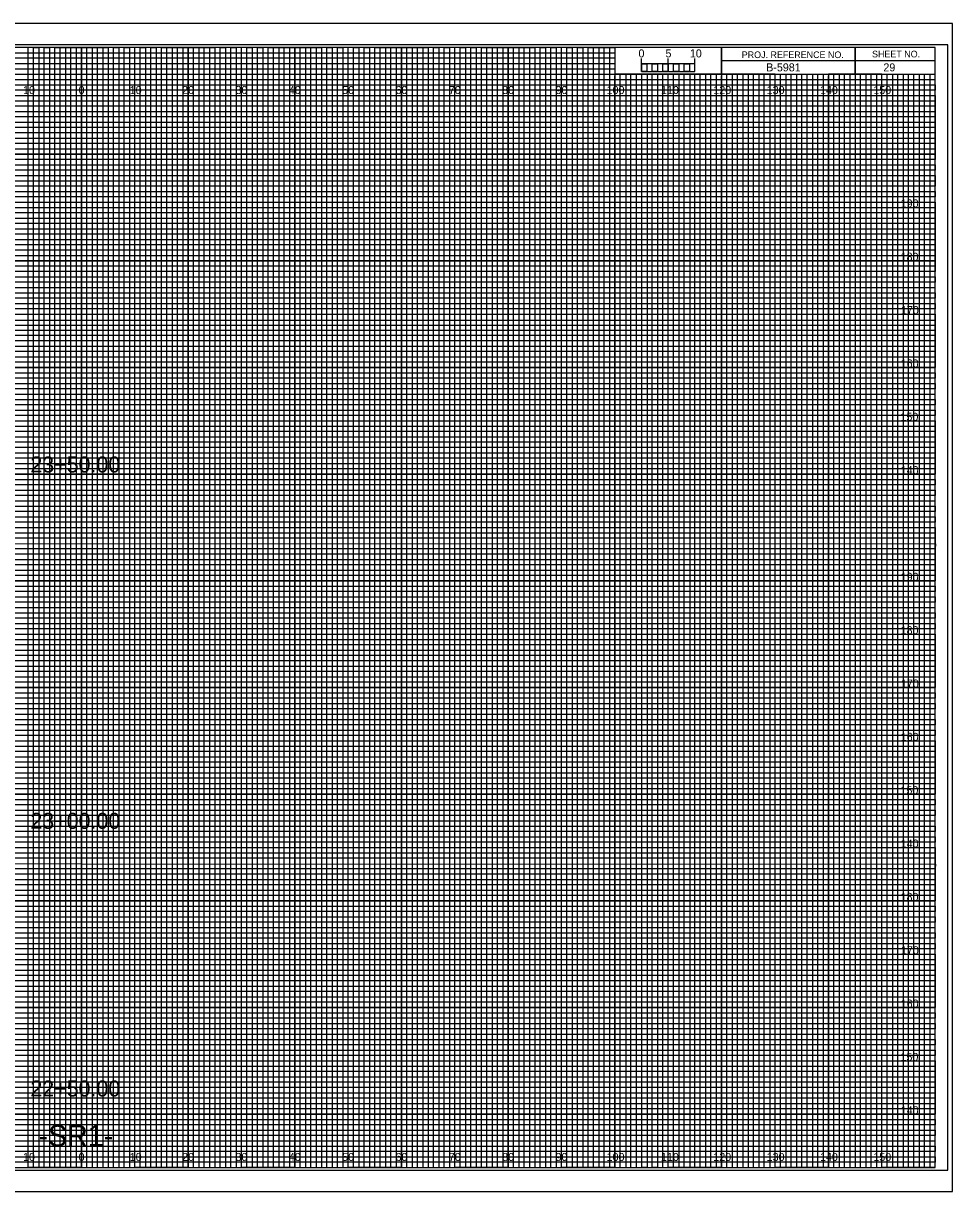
# Model space of a CAD drawing. Extents: x -13 to 323, y -5 to 654.
# Drawn here: x 149.1 to 323.3, y 215.5 to 434.5 of the extents above; entities that cross this region are included whole.
import ezdxf

# ---------------------------------------------------------------- set-up
doc = ezdxf.new("R2010")
doc.units = 0
for name, color, linetype in [('Exist Cross Section Cell', 7, 'Continuous'), ('Exist XS Center Line Elevation Label', 7, 'Continuous'), ('Exist XS Ground Line', 7, 'Continuous'), ('Prop CMT Concrete Structures', 7, 'Continuous'), ('Prop CMT Guardrail Graphics', 7, 'Continuous'), ('Prop CMT Pvmt Course 1', 7, 'Continuous'), ('Prop CMT Pvmt Course 2', 7, 'Continuous'), ('Prop CMT Pvmt Course 3', 7, 'Continuous'), ('Prop CMT Pvmt Surface', 7, 'Continuous'), ('Prop CMT Shld Paved Course 1', 7, 'Continuous'), ('Prop CMT Shld Paved Course 2', 7, 'Continuous'), ('Prop CMT Shld Paved Course 3', 7, 'Continuous'), ('Prop CMT Subgrade Earthwork', 7, 'Continuous'), ('Prop XS Ditch Standard Text', 7, 'Continuous'), ('Prop XS SE Text', 7, 'Continuous'), ('Prop XS Side Slope Text', 7, 'Continuous'), ('Scratch_Level_0', 7, 'Continuous')]:
    doc.layers.add(name, color=color, linetype=linetype)

msp = doc.modelspace()

# ---------------------------------------------------------------- linework, layer by layer
at = {"layer": 'Exist XS Center Line Elevation Label'}
for points in [[(145, 220), (155, 220), (155, 430), (165, 430), (165, 220), (175, 220), (175, 430), (185, 430), (185, 220), (195, 220), (195, 430), (205, 430), (205, 220), (215, 220), (215, 430), (225, 430), (225, 220), (235, 220), (235, 430), (245, 430), (245, 220), (255, 220), (255, 430), (259.93, 430), (260, 430), (260, 425), (264.99, 425), (264.99, 220), (275, 220), (275, 425), (285, 425), (285, 220), (295, 220), (295, 425), (305, 425), (305, 220), (315, 220), (315, 425)], [(0, 425), (275, 425)], [(0, 405), (320, 405), (320, 415), (0, 415)], [(0, 385), (320, 385), (320, 395), (0, 395)], [(0, 365), (320, 365), (320, 375), (0, 375)], [(0, 345), (320, 345), (320, 355), (0, 355)], [(0, 325), (320, 325), (320, 335), (0, 335)], [(0, 305), (320, 305), (320, 315), (0, 315)], [(0, 285), (320, 285), (320, 295), (0, 295)], [(0, 265), (320, 265), (320, 275), (0, 275)], [(0, 245), (320, 245), (320, 255), (0, 255)], [(0, 225), (320, 225), (320, 235), (0, 235)]]:
    msp.add_lwpolyline(points, dxfattribs=at)
at = {"layer": 'Exist XS Ground Line'}
for p, q in [((150, 430), (140, 430)), ((150, 220), (150, 430)), ((170, 430), (160, 430)), ((160, 430), (160, 220)), ((170, 220), (170, 430)), ((190, 430), (180, 430)), ((180, 430), (180, 220)), ((190, 220), (190, 430)), ((210, 430), (200, 430)), ((200, 430), (200, 220)), ((210, 220), (210, 430)), ((230, 430), (220, 430)), ((220, 430), (220, 220)), ((230, 220), (230, 430)), ((250, 430), (240, 430)), ((240, 430), (240, 220)), ((250, 220), (250, 430)), ((260, 430), (260, 220)), ((270, 220), (270, 425)), ((290, 425), (280, 425)), ((280, 425), (280, 220)), ((290, 220), (290, 425)), ((310, 425), (300, 425)), ((300, 425), (300, 220)), ((310, 220), (310, 425)), ((160, 220), (150, 220)), ((180, 220), (170, 220)), ((200, 220), (190, 220)), ((220, 220), (210, 220)), ((240, 220), (230, 220)), ((260, 220), (250, 220)), ((280, 220), (270, 220)), ((300, 220), (290, 220)), ((320, 220), (310, 220)), ((320, 220), (320, 220))]:
    msp.add_line(p, q, dxfattribs=at)
for points in [[(0, 420), (320, 420), (320, 410), (0, 410)], [(0, 400), (320, 400), (320, 390), (0, 390)], [(0, 380), (320, 380), (320, 370), (0, 370)], [(0, 360), (320, 360), (320, 350), (0, 350)], [(0, 340), (320, 340), (320, 330), (0, 330)], [(0, 320), (320, 320), (320, 310), (0, 310)], [(0, 300), (320, 300), (320, 290), (0, 290)], [(0, 280), (320, 280), (320, 270), (0, 270)], [(0, 260), (320, 260), (320, 250), (0, 250)], [(0, 240), (320, 240), (320, 230), (0, 230)]]:
    msp.add_lwpolyline(points, dxfattribs=at)
at = {"layer": 'Prop CMT Pvmt Course 1'}
for p, q in [((323.3, 434.5), (-13.4, 434.5)), ((-13.4, 215.5), (323.3, 215.5))]:
    msp.add_line(p, q, dxfattribs=at)
at = {"layer": 'Prop CMT Pvmt Course 2'}
msp.add_lwpolyline([(-13.4, 215.5), (323.3, 215.5), (323.3, 434.5), (-13.4, 434.5)], close=True, dxfattribs=at)
at = {"layer": 'Prop CMT Pvmt Course 3'}
msp.add_lwpolyline([(-10.8, 219.5), (322.4, 219.5), (322.4, 430.5), (-10.8, 430.5)], close=True, dxfattribs=at)
at = {"layer": 'Prop CMT Shld Paved Course 1'}
for p, q in [((305, 430), (305, 425)), ((305, 425), (305, 430)), ((280, 427.5), (280, 425)), ((320, 427.49), (280, 427.49)), ((280, 425), (320, 425))]:
    msp.add_line(p, q, dxfattribs=at)
for points in [[(320, 430), (0, 430), (0, 220), (320, 220)], [(280, 430), (260, 430), (260, 425.03), (280, 425.03)], [(320, 430), (280, 430), (280, 425), (320, 425)]]:
    msp.add_lwpolyline(points, close=True, dxfattribs=at)
at = {"layer": 'Prop CMT Shld Paved Course 2'}
for p, q in [((267, 425), (266.01, 425)), ((266.01, 425), (266.01, 220)), ((267, 220), (267, 425)), ((269, 425), (268, 425)), ((268, 425), (268, 220)), ((269, 220), (269, 425)), ((266.01, 220), (265, 220)), ((268, 220), (267, 220))]:
    msp.add_line(p, q, dxfattribs=at)
for points in [[(150, 220), (151, 220), (151, 430), (152, 430), (152, 220)], [(152, 220), (153, 220), (153, 430), (154, 430), (154, 220)], [(155, 220), (156, 220), (156, 430), (157, 430), (157, 220)], [(157, 220), (158, 220), (158, 430), (159, 430), (159, 220)], [(160, 220), (161, 220), (161, 430), (162, 430), (162, 220)], [(162, 220), (163, 220), (163, 430), (164, 430), (164, 220)], [(165, 220), (166, 220), (166, 430), (167, 430), (167, 220)], [(167, 220), (168, 220), (168, 430), (169, 430), (169, 220)], [(170, 220), (171, 220), (171, 430), (172, 430), (172, 220)], [(172, 220), (173, 220), (173, 430), (174, 430), (174, 220)], [(175, 220), (176, 220), (176, 430), (177, 430), (177, 220)], [(177, 220), (178, 220), (178, 430), (179, 430), (179, 220)], [(180, 220), (181, 220), (181, 430), (182, 430), (182, 220)], [(182, 220), (183, 220), (183, 430), (184, 430), (184, 220)], [(185, 220), (186, 220), (186, 430), (187, 430), (187, 220)], [(187, 220), (188, 220), (188, 430), (189, 430), (189, 220)], [(190, 220), (191, 220), (191, 430), (192, 430), (192, 220)], [(192, 220), (193, 220), (193, 430), (194, 430), (194, 220)], [(195, 220), (196, 220), (196, 430), (197, 430), (197, 220)], [(197, 220), (198, 220), (198, 430), (199, 430), (199, 220)], [(200, 220), (201, 220), (201, 430), (202, 430), (202, 220)], [(202, 220), (203, 220), (203, 430), (204, 430), (204, 220)], [(205, 220), (206, 220), (206, 430), (207, 430), (207, 220)], [(207, 220), (208, 220), (208, 430), (209, 430), (209, 220)], [(210, 220), (211, 220), (211, 430), (212, 430), (212, 220)], [(212, 220), (213, 220), (213, 430), (214, 430), (214, 220)], [(215, 220), (216, 220), (216, 430), (217, 430), (217, 220)], [(217, 220), (218, 220), (218, 430), (219, 430), (219, 220)], [(220, 220), (221, 220), (221, 430), (222, 430), (222, 220)], [(222, 220), (223, 220), (223, 430), (224, 430), (224, 220)], [(225, 220), (226, 220), (226, 430), (227, 430), (227, 220)], [(227, 220), (228, 220), (228, 430), (229, 430), (229, 220)], [(230, 220), (231, 220), (231, 430), (232, 430), (232, 220)], [(232, 220), (233, 220), (233, 430), (234, 430), (234, 220)], [(235, 220), (236, 220), (236, 430), (237, 430), (237, 220)], [(237, 220), (238, 220), (238, 430), (239, 430), (239, 220)], [(240, 220), (241, 220), (241, 430), (242, 430), (242, 220)], [(242, 220), (243, 220), (243, 430), (244, 430), (244, 220)], [(245, 220), (246, 220), (246, 430), (247, 430), (247, 220)], [(247, 220), (248, 220), (248, 430), (249, 430), (249, 220)], [(250, 220), (251, 220), (251, 430), (252, 430), (252, 220)], [(252, 220), (253, 220), (253, 430), (254, 430), (254, 220)], [(255, 220), (256, 220), (256, 430), (257, 430), (257, 220)], [(257, 220), (258, 220), (258, 430), (259, 430), (259, 220)], [(260, 220), (261, 220), (261, 425), (262.02, 425), (262.02, 220)], [(262, 220), (263, 220), (263, 425), (263.99, 425), (263.99, 220)], [(270, 220), (270.98, 220), (270.98, 425), (272, 425), (272, 220)], [(272, 220), (273, 220), (273, 425), (274.05, 425), (274.05, 220)], [(275, 220), (276, 220), (276, 425), (277, 425), (277, 220)], [(277, 220), (278, 220), (278, 425), (279, 425), (279, 220)], [(280, 220), (281, 220), (281, 425), (282, 425), (282, 220)], [(282, 220), (283, 220), (283, 425), (284, 425), (284, 220)], [(285, 220), (286, 220), (286, 425), (287, 425), (287, 220)], [(287, 220), (288, 220), (288, 425), (289, 425), (289, 220)], [(290, 220), (291, 220), (291, 425), (292, 425), (292, 220)], [(292, 220), (293, 220), (293, 425), (294, 425), (294, 220)], [(295, 220), (296, 220), (296, 425), (297, 425), (297, 220)], [(297, 220), (298, 220), (298, 425), (299, 425), (299, 220)], [(300, 220), (301, 220), (301, 425), (302, 425), (302, 220)], [(302, 220), (303, 220), (303, 425), (304, 425), (304, 220)], [(305, 220), (306, 220), (306, 425), (307, 425), (307, 220)], [(307, 220), (308, 220), (308, 425), (309, 425), (309, 220)], [(310, 220), (311, 220), (311, 425), (312, 425), (312, 220)], [(312, 220), (313, 220), (313, 425), (314, 425), (314, 220)], [(315, 220), (316, 220), (316, 425), (317, 425), (317, 220)], [(317, 220), (318, 220), (318, 425), (319, 425), (319, 220)]]:
    msp.add_lwpolyline(points, dxfattribs=at)
at = {"layer": 'Prop CMT Shld Paved Course 3'}
for p, q in [((265, 425.49), (265, 427.9)), ((265, 426.9), (265, 427.9)), ((270, 425.49), (270, 427.9)), ((275, 425.49), (275, 427.9)), ((275, 426.9), (275, 427.9))]:
    msp.add_line(p, q, dxfattribs=at)
for points in [[(275, 426.9), (265, 426.9), (265, 425.49), (275, 425.49)], [(265, 426.9), (266, 426.9), (266, 425.49), (265, 425.49)], [(267, 426.9), (268, 426.9), (268, 425.49), (267, 425.49)], [(269, 426.9), (270, 426.9), (270, 425.49), (269, 425.49)], [(271, 426.9), (272, 426.9), (272, 425.49), (271, 425.49)], [(273, 426.9), (274, 426.9), (274, 425.49), (273, 425.49)]]:
    msp.add_lwpolyline(points, close=True, dxfattribs=at)
at = {"layer": 'Prop CMT Subgrade Earthwork'}
for p, q in [((150, 220), (150, 430)), ((160, 220), (160, 430)), ((170, 220), (170, 430)), ((180, 220), (180, 430)), ((190, 220), (190, 430)), ((200, 220), (200, 430)), ((210, 220), (210, 430)), ((220, 220), (220, 430)), ((230, 220), (230, 430)), ((240, 220), (240, 430)), ((250, 220), (250, 430)), ((260, 220), (260, 424.69)), ((270, 220), (270, 424.69)), ((280, 220), (280, 424.69)), ((290, 220), (290, 424.69)), ((300, 220), (300, 424.69)), ((310, 220), (310, 424.69)), ((0, 420), (320, 420)), ((0, 410), (320, 410)), ((0, 400), (320, 400)), ((0, 390), (320, 390)), ((0, 380), (320, 380)), ((0, 370), (320, 370)), ((0, 360), (320, 360)), ((0, 350), (320, 350)), ((0, 340), (320, 340)), ((0, 330), (320, 330)), ((0, 320), (320, 320)), ((0, 310), (320, 310)), ((0, 300), (320, 300)), ((0, 290), (320, 290)), ((0, 280), (320, 280)), ((0, 270), (320, 270)), ((0, 260), (320, 260)), ((0, 250), (320, 250)), ((0, 240), (320, 240)), ((0, 230), (320, 230))]:
    msp.add_line(p, q, dxfattribs=at)
at = {"layer": 'Scratch_Level_0'}
for p, q in [((0, 429), (260, 429)), ((260, 427.98), (0, 427.98)), ((260, 429), (260, 427.98)), ((0, 427), (260, 427)), ((260, 425.89), (0, 425.89)), ((260, 427), (260, 425.89)), ((0, 424), (320, 424))]:
    msp.add_line(p, q, dxfattribs=at)
for points in [[(0, 423), (270, 423), (320, 423), (320, 422), (0, 422)], [(0, 421), (320, 421), (320, 419), (0, 419)], [(0, 418), (320, 418), (320, 417), (0, 416.98)], [(0, 416), (320, 416), (320, 414), (0, 414)], [(0, 413), (320, 413), (320, 412), (0, 412)], [(0, 411), (320, 411), (320, 409), (0, 409)], [(0, 408), (320, 408), (320, 407), (0, 407)], [(0, 406), (320, 406), (320, 404), (0, 404)], [(0, 403), (320, 403), (320, 402), (0, 402)], [(0, 401), (320, 401), (320, 399), (0, 399)], [(0, 398), (320, 398), (320, 397), (0, 397)], [(0, 396), (320, 396), (320, 393.95), (320, 393), (320, 392), (0, 392)], [(0, 394), (320, 394), (320, 393), (0, 393)], [(0, 391), (320, 391), (320, 389), (0, 389.03)], [(0, 389.03), (320, 389), (320, 388), (0, 388)], [(0, 387), (320, 387), (320, 386), (0, 386)], [(0, 384), (320, 384), (320, 383), (0, 383)], [(0, 382), (320, 382), (320, 381), (0, 381)], [(-0.07, 378.89), (320, 378.89), (320, 377.88), (-0.07, 377.88)], [(0, 377), (320, 377), (320, 376), (0, 376)], [(0, 374), (320, 374), (320, 373), (0, 373)], [(0, 372), (320, 372), (320, 371), (0, 371)], [(0, 369), (320, 369), (320, 368), (0, 368)], [(0, 367), (320, 367), (320, 366), (0, 366)], [(0, 364), (320, 364), (320, 363), (0, 363)], [(0, 362), (320, 362), (320, 361), (0, 361)], [(0, 359), (320, 359), (319.99, 357.98), (0, 358)], [(0, 357), (320, 357), (320, 356), (0, 356)], [(0, 354), (320, 354), (320, 353), (0, 353)], [(0, 352), (320, 352), (320, 351), (0, 351)], [(0, 349), (320, 349), (320, 348), (0, 348)], [(0, 347), (320, 347), (320, 346), (0, 346)], [(0, 344), (320, 344), (320, 343), (0, 343)], [(0, 342), (320, 342), (320, 341), (0, 341)], [(0, 339), (320, 339), (320, 338), (0, 338)], [(0, 336.99), (320.07, 336.91), (320, 336), (0, 336)], [(0, 334), (320, 334), (320, 333), (0, 333)], [(0, 332), (320, 332), (320, 331), (0, 331)], [(0, 329), (320, 329), (320, 328), (0, 328)], [(0, 327), (320, 327), (320, 326), (0, 326)], [(0, 324), (320, 324), (320, 323), (0, 323)], [(0, 322), (320, 322), (320, 321), (0, 321)], [(0, 319), (320, 319), (320, 318), (0, 318)], [(0, 317), (320, 317), (320, 316), (0, 316)], [(0, 314), (320, 314), (320, 313), (0, 313)], [(0, 312), (320, 312), (320, 311), (0, 311)], [(0, 309), (320, 309), (320, 308), (0, 308)], [(0, 307), (320, 307), (320, 306), (0, 306)], [(0, 304), (320, 304), (320, 303), (0, 303)], [(0, 302), (320, 302), (320, 301), (0, 301)], [(0, 299), (320, 299), (319.99, 297.98), (0, 298)], [(0, 297), (320, 297), (320, 296), (0, 296)], [(0, 294), (320, 294), (320, 293), (0, 293)], [(0, 292), (320, 292), (320, 291), (0, 291)], [(0, 289), (320, 289), (320, 288), (0, 288)], [(0, 287), (320, 287), (320, 286), (0, 286)], [(0, 284), (320, 284), (320, 283), (0, 283)], [(0, 282), (320, 282), (320, 281), (0, 281)], [(0, 279), (320, 279), (320, 278), (0, 278)], [(0, 276.99), (320.07, 276.91), (320, 276), (0, 276)], [(0, 274), (320, 274), (320, 273), (0, 273)], [(0, 272), (320, 272), (320, 271), (0, 271)], [(0, 269), (320, 269), (320, 268), (0, 268)], [(0, 267), (320, 267), (320, 266), (0, 266)], [(0, 264), (320, 264), (320, 263), (0, 263)], [(0, 262), (320, 262), (320, 261), (0, 261)], [(0, 259), (320, 259), (320, 258), (0, 258)], [(0, 257), (320, 257), (320, 256), (0, 256)], [(0, 254), (320, 254), (320, 253), (0, 253)], [(0, 252), (320, 252), (320, 251), (0, 251)], [(0, 249), (320, 249), (320, 248), (0, 248)], [(0, 247), (320, 247), (320, 246), (0, 246)], [(0, 244), (320, 244), (320, 243), (0, 243)], [(0, 242), (320, 242), (320, 241), (0, 241)], [(0, 239), (320, 239), (320, 238), (0, 238)], [(0, 237), (320, 237), (320, 236), (0, 236)], [(0, 234), (320, 234), (320, 233), (0, 233)], [(0, 232), (320, 232), (320, 231), (0, 231)], [(0, 229), (320, 229), (320, 228), (0, 228)], [(0, 227), (320, 227), (320, 226), (0, 226)], [(0, 224), (320, 224), (320, 223), (0, 223)], [(0, 222), (320, 222), (320, 221), (0, 221)]]:
    msp.add_lwpolyline(points, dxfattribs=at)

# ---------------------------------------------------------------- texts
at = {"layer": 'Exist Cross Section Cell'}
for s, p in [('10', (149.04, 421.25)), ('0', (159.45, 421.25)), ('0', (159.45, 421.25)), ('10', (169.04, 421.25)), ('20', (178.86, 421.25)), ('30', (188.86, 421.25)), ('40', (198.86, 421.25)), ('50', (208.86, 421.25)), ('60', (218.86, 421.25)), ('70', (228.86, 421.25)), ('80', (238.86, 421.25)), ('90', (248.86, 421.25)), ('100', (258.44, 421.25)), ('110', (268.62, 421.25)), ('120', (278.44, 421.25)), ('130', (288.44, 421.25)), ('140', (298.44, 421.25)), ('150', (308.44, 421.25)), ('10', (149.04, 221.25)), ('0', (159.45, 221.25)), ('0', (159.45, 221.25)), ('10', (169.04, 221.25)), ('20', (178.86, 221.25)), ('30', (188.86, 221.25)), ('40', (198.86, 221.25)), ('50', (208.86, 221.25)), ('60', (218.86, 221.25)), ('70', (228.86, 221.25)), ('80', (238.86, 221.25)), ('90', (248.86, 221.25)), ('100', (258.44, 221.25)), ('110', (268.62, 221.25)), ('120', (278.44, 221.25)), ('130', (288.44, 221.25)), ('140', (298.44, 221.25)), ('150', (308.44, 221.25))]:
    msp.add_text(s, height=1.5, dxfattribs=at).set_placement(p)
at = {"layer": 'Prop CMT Concrete Structures'}
for s, p in [('23+50.00', (150.41, 350.31)), ('23+00.00', (150.41, 283.51)), ('22+50.00', (150.41, 233.34))]:
    msp.add_text(s, height=3, dxfattribs=at).set_placement(p)
at = {"layer": 'Prop CMT Guardrail Graphics'}
for s, p in [('190', (313.57, 400)), ('180', (313.55, 390)), ('170', (313.61, 380)), ('160', (313.57, 370)), ('150', (313.52, 360)), ('140', (313.57, 350)), ('190', (313.57, 330)), ('180', (313.55, 320)), ('170', (313.61, 310)), ('160', (313.57, 300)), ('150', (313.52, 290)), ('140', (313.57, 280)), ('180', (313.55, 270)), ('170', (313.61, 260)), ('160', (313.57, 250)), ('150', (313.52, 240)), ('140', (313.57, 230))]:
    msp.add_text(s, height=1.5, dxfattribs=at).set_placement(p)
at = {"layer": 'Prop CMT Pvmt Surface'}
for s, p in [('5', (269.47, 428.12)), ('10', (274.04, 428.12))]:
    msp.add_text(s, height=1.5, dxfattribs=at).set_placement(p)
at = {"layer": 'Prop CMT Shld Paved Course 1'}
for s, p in [('PROJ. REFERENCE NO.', (283.77, 427.99)), ('SHEET NO.', (308.19, 428.12))]:
    msp.add_text(s, height=1.25, dxfattribs=at).set_placement(p)
at = {"layer": 'Prop CMT Shld Paved Course 3'}
msp.add_text('0', height=1.5, dxfattribs=at).set_placement((264.41, 428.12))
at = {"layer": 'Prop XS Ditch Standard Text'}
msp.add_text('-SR1-', height=4, dxfattribs=at).set_placement((151.95, 224))
at = {"layer": 'Prop XS SE Text'}
msp.add_text(' B-5981', height=1.5, dxfattribs=at).set_placement((287.79, 425.5))
at = {"layer": 'Prop XS Side Slope Text'}
msp.add_text('29', height=1.5, dxfattribs=at).set_placement((310.32, 425.5))

doc.saveas('drawing.dxf')
